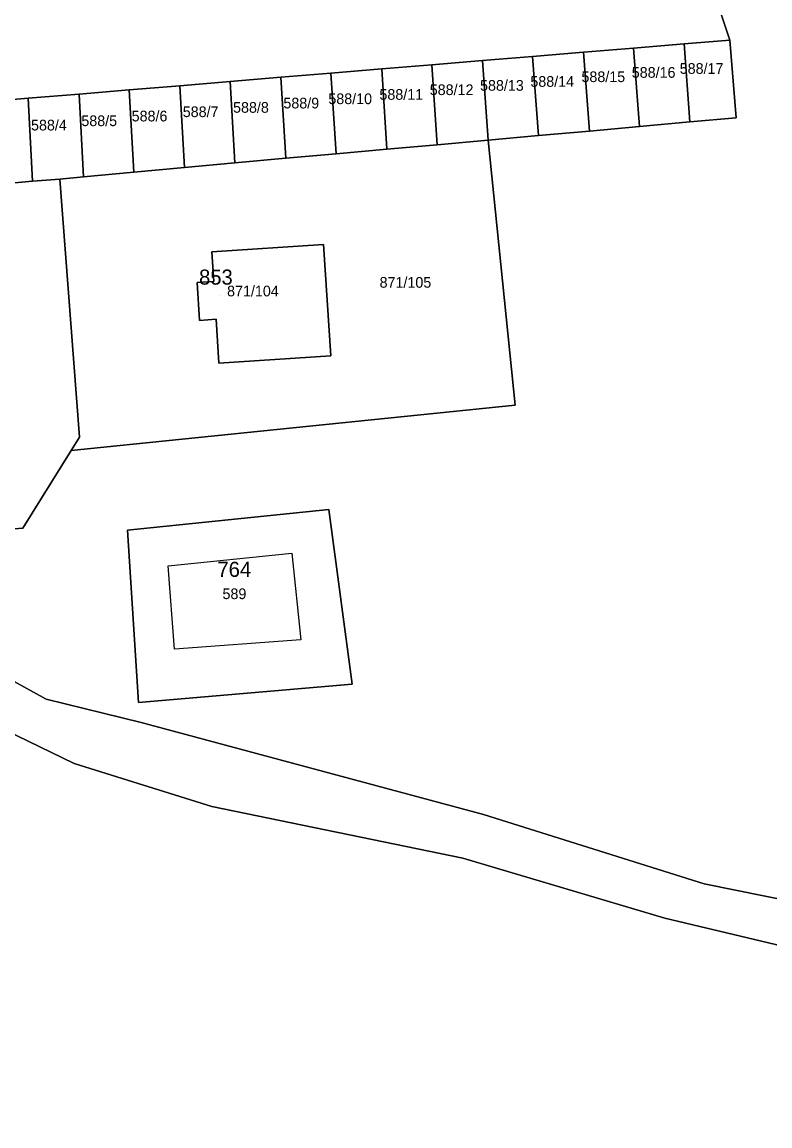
# Model space of a CAD drawing. Extents: x -873642 to -872917, y -1012962 to -1012567.
# Drawn here: x -873069.4 to -873009.9, y -1012787.3 to -1012699.6 of the extents above; entities that cross this region are included whole.
import ezdxf

# ---------------------------------------------------------------- set-up
doc = ezdxf.new("R2010")
doc.units = 0
for name, color, linetype in [('adresni_misto', 7, 'Continuous'), ('cisla_parcelni_kn', 7, 'Continuous'), ('cislo_domovni', 7, 'Continuous'), ('parcely_kn', 7, 'Continuous'), ('stavebni_objekty_bydleni', 7, 'Continuous'), ('stavebni_objekty_ostatni', 7, 'Continuous'), ('stavebni_objekty_vyroba', 7, 'Continuous')]:
    doc.layers.add(name, color=color, linetype=linetype)

msp = doc.modelspace()

# ---------------------------------------------------------------- linework, layer by layer
at = {"layer": 'adresni_misto'}
for p, q in [((-873053.71, -1012721.33), (-873053.71, -1012721.33)), ((-873052.25, -1012744.56), (-873052.25, -1012744.56))]:
    msp.add_line(p, q, dxfattribs=at)
at = {"layer": 'parcely_kn'}
for points in [[(-873074.59, -1012740.17), (-873069.33, -1012739.79), (-873065.48, -1012733.61), (-873030.18, -1012730.01), (-873032.33, -1012708.94), (-873028.33, -1012708.58), (-873024.28, -1012708.22), (-873020.29, -1012707.86), (-873016.29, -1012707.5), (-873012.61, -1012707.16), (-873013.12, -1012701), (-873016.82, -1012689.87), (-873017.19, -1012683.08), (-873019.32, -1012668.75), (-873020.42, -1012661.39), (-873025.64, -1012651.97), (-873026.14, -1012645.58), (-872990.98, -1012635.74)], [(-873074.59, -1012740.17), (-873069.33, -1012739.79), (-873065.48, -1012733.61), (-873030.18, -1012730.01), (-873032.33, -1012708.94), (-873028.33, -1012708.58), (-873024.28, -1012708.22), (-873020.29, -1012707.86), (-873016.29, -1012707.5), (-873012.61, -1012707.16), (-873013.12, -1012701), (-873016.82, -1012689.87), (-873017.19, -1012683.08), (-873019.32, -1012668.75), (-873020.42, -1012661.39), (-873025.64, -1012651.97), (-873026.14, -1012645.58), (-872990.98, -1012635.74)], [(-873016.82, -1012689.87), (-873013.12, -1012701), (-873016.73, -1012701.3), (-873020.77, -1012701.63), (-873024.75, -1012701.96), (-873028.79, -1012702.29), (-873032.77, -1012702.62), (-873036.81, -1012702.96), (-873040.79, -1012703.29), (-873044.83, -1012703.62), (-873048.81, -1012703.95), (-873052.85, -1012704.29), (-873056.83, -1012704.62), (-873060.87, -1012704.95), (-873064.85, -1012705.28), (-873068.89, -1012705.62), (-873072.87, -1012705.95)], [(-873016.82, -1012689.87), (-873013.12, -1012701), (-873016.73, -1012701.3), (-873020.77, -1012701.63), (-873024.75, -1012701.96), (-873028.79, -1012702.29), (-873032.77, -1012702.62), (-873036.81, -1012702.96), (-873040.79, -1012703.29), (-873044.83, -1012703.62), (-873048.81, -1012703.95), (-873052.85, -1012704.29), (-873056.83, -1012704.62), (-873060.87, -1012704.95), (-873064.85, -1012705.28), (-873068.89, -1012705.62), (-873072.87, -1012705.95)], [(-872958.67, -1012787.72), (-872975.04, -1012782.47), (-872991.42, -1012777.17), (-873018.29, -1012770.78), (-873034.35, -1012766.02), (-873054.3, -1012761.9), (-873065.25, -1012758.5), (-873079.89, -1012751.4), (-873100.03, -1012737.92), (-873105.65, -1012736.17), (-873101.03, -1012731.11), (-873099.7, -1012729.49), (-873098.43, -1012730.03), (-873097.94, -1012733.42), (-873081.4, -1012745.11), (-873078.44, -1012747.33), (-873067.46, -1012753.38), (-873059.91, -1012755.24), (-873032.7, -1012762.55), (-873015.14, -1012768.05), (-872991.17, -1012772.9), (-872969.11, -1012779.09), (-872954.48, -1012785.31), (-872943.22, -1012794.81)], [(-872958.67, -1012787.72), (-872975.04, -1012782.47), (-872991.42, -1012777.17), (-873018.29, -1012770.78), (-873034.35, -1012766.02), (-873054.3, -1012761.9), (-873065.25, -1012758.5), (-873079.89, -1012751.4), (-873100.03, -1012737.92), (-873105.65, -1012736.17), (-873101.03, -1012731.11), (-873099.7, -1012729.49), (-873098.43, -1012730.03), (-873097.94, -1012733.42), (-873081.4, -1012745.11), (-873078.44, -1012747.33), (-873067.46, -1012753.38), (-873059.91, -1012755.24), (-873032.7, -1012762.55), (-873015.14, -1012768.05), (-872991.17, -1012772.9), (-872969.11, -1012779.09), (-872954.48, -1012785.31), (-872943.22, -1012794.81)], [(-873185.58, -1012756.25), (-873148.18, -1012749.22), (-873135.01, -1012746.72), (-873122.26, -1012744.11), (-873114.5, -1012741.96), (-873110.07, -1012739.5), (-873105.65, -1012736.17), (-873100.03, -1012737.92), (-873079.89, -1012751.4), (-873065.25, -1012758.5), (-873054.3, -1012761.9), (-873034.35, -1012766.02), (-873018.29, -1012770.78), (-872991.42, -1012777.17), (-872975.04, -1012782.47), (-872958.67, -1012787.72)], [(-873185.58, -1012756.25), (-873148.18, -1012749.22), (-873135.01, -1012746.72), (-873122.26, -1012744.11), (-873114.5, -1012741.96), (-873110.07, -1012739.5), (-873105.65, -1012736.17), (-873100.03, -1012737.92), (-873079.89, -1012751.4), (-873065.25, -1012758.5), (-873054.3, -1012761.9), (-873034.35, -1012766.02), (-873018.29, -1012770.78), (-872991.42, -1012777.17), (-872975.04, -1012782.47), (-872958.67, -1012787.72)], [(-872991.17, -1012772.9), (-873015.14, -1012768.05), (-873032.7, -1012762.55), (-873059.91, -1012755.24), (-873067.46, -1012753.38), (-873078.44, -1012747.33)], [(-872991.17, -1012772.9), (-873015.14, -1012768.05), (-873032.7, -1012762.55), (-873059.91, -1012755.24), (-873067.46, -1012753.38), (-873078.44, -1012747.33)]]:
    msp.add_lwpolyline(points, dxfattribs=at)
for points in [[(-873012.61, -1012707.16), (-873016.29, -1012707.5), (-873016.73, -1012701.3), (-873013.12, -1012701)], [(-873012.61, -1012707.16), (-873016.29, -1012707.5), (-873016.73, -1012701.3), (-873013.12, -1012701)], [(-873024.75, -1012701.96), (-873024.28, -1012708.22), (-873028.33, -1012708.58), (-873028.79, -1012702.29)], [(-873024.75, -1012701.96), (-873024.28, -1012708.22), (-873028.33, -1012708.58), (-873028.79, -1012702.29)], [(-873020.77, -1012701.63), (-873020.29, -1012707.86), (-873024.28, -1012708.22), (-873024.75, -1012701.96)], [(-873020.77, -1012701.63), (-873020.29, -1012707.86), (-873024.28, -1012708.22), (-873024.75, -1012701.96)], [(-873016.73, -1012701.3), (-873016.29, -1012707.5), (-873020.29, -1012707.86), (-873020.77, -1012701.63)], [(-873016.73, -1012701.3), (-873016.29, -1012707.5), (-873020.29, -1012707.86), (-873020.77, -1012701.63)], [(-873032.77, -1012702.62), (-873032.33, -1012708.94), (-873036.38, -1012709.31), (-873036.81, -1012702.96)], [(-873032.77, -1012702.62), (-873032.33, -1012708.94), (-873036.38, -1012709.31), (-873036.81, -1012702.96)], [(-873028.79, -1012702.29), (-873028.33, -1012708.58), (-873032.33, -1012708.94), (-873032.77, -1012702.62)], [(-873028.79, -1012702.29), (-873028.33, -1012708.58), (-873032.33, -1012708.94), (-873032.77, -1012702.62)], [(-873044.83, -1012703.62), (-873044.42, -1012710.03), (-873048.42, -1012710.39), (-873048.81, -1012703.95)], [(-873044.83, -1012703.62), (-873044.42, -1012710.03), (-873048.42, -1012710.39), (-873048.81, -1012703.95)], [(-873040.79, -1012703.29), (-873040.37, -1012709.67), (-873044.42, -1012710.03), (-873044.83, -1012703.62)], [(-873040.79, -1012703.29), (-873040.37, -1012709.67), (-873044.42, -1012710.03), (-873044.83, -1012703.62)], [(-873036.81, -1012702.96), (-873036.38, -1012709.31), (-873040.37, -1012709.67), (-873040.79, -1012703.29)], [(-873036.81, -1012702.96), (-873036.38, -1012709.31), (-873040.37, -1012709.67), (-873040.79, -1012703.29)], [(-873056.83, -1012704.62), (-873056.46, -1012711.12), (-873060.51, -1012711.48), (-873060.87, -1012704.95)], [(-873056.83, -1012704.62), (-873056.46, -1012711.12), (-873060.51, -1012711.48), (-873060.87, -1012704.95)], [(-873052.85, -1012704.29), (-873052.47, -1012710.76), (-873056.46, -1012711.12), (-873056.83, -1012704.62)], [(-873052.85, -1012704.29), (-873052.47, -1012710.76), (-873056.46, -1012711.12), (-873056.83, -1012704.62)], [(-873048.81, -1012703.95), (-873048.42, -1012710.39), (-873052.47, -1012710.76), (-873052.85, -1012704.29)], [(-873048.81, -1012703.95), (-873048.42, -1012710.39), (-873052.47, -1012710.76), (-873052.85, -1012704.29)], [(-873064.85, -1012705.28), (-873064.51, -1012711.85), (-873066.38, -1012712.05), (-873068.55, -1012712.21), (-873068.89, -1012705.62)], [(-873064.85, -1012705.28), (-873064.51, -1012711.85), (-873066.38, -1012712.05), (-873068.55, -1012712.21), (-873068.89, -1012705.62)], [(-873060.87, -1012704.95), (-873060.51, -1012711.48), (-873064.51, -1012711.85), (-873064.85, -1012705.28)], [(-873060.87, -1012704.95), (-873060.51, -1012711.48), (-873064.51, -1012711.85), (-873064.85, -1012705.28)], [(-873068.89, -1012705.62), (-873068.55, -1012712.21), (-873071.45, -1012712.46), (-873072.55, -1012712.57), (-873072.87, -1012705.95)], [(-873068.89, -1012705.62), (-873068.55, -1012712.21), (-873071.45, -1012712.46), (-873072.55, -1012712.57), (-873072.87, -1012705.95)], [(-873065.48, -1012733.61), (-873064.82, -1012732.54), (-873066.38, -1012712.05), (-873064.51, -1012711.85), (-873060.51, -1012711.48), (-873056.46, -1012711.12), (-873052.47, -1012710.76), (-873048.42, -1012710.39), (-873044.42, -1012710.03), (-873040.37, -1012709.67), (-873036.38, -1012709.31), (-873032.33, -1012708.94), (-873030.18, -1012730.01)], [(-873065.48, -1012733.61), (-873064.82, -1012732.54), (-873066.38, -1012712.05), (-873064.51, -1012711.85), (-873060.51, -1012711.48), (-873056.46, -1012711.12), (-873052.47, -1012710.76), (-873048.42, -1012710.39), (-873044.42, -1012710.03), (-873040.37, -1012709.67), (-873036.38, -1012709.31), (-873032.33, -1012708.94), (-873030.18, -1012730.01)], [(-873071.45, -1012712.46), (-873068.55, -1012712.21), (-873066.38, -1012712.05), (-873064.82, -1012732.54), (-873065.48, -1012733.61), (-873069.33, -1012739.79), (-873074.59, -1012740.17), (-873098.43, -1012730.03), (-873099.7, -1012729.49), (-873097.47, -1012726.79), (-873090.67, -1012727.04), (-873069.98, -1012725.86), (-873070.53, -1012720.91)], [(-873071.45, -1012712.46), (-873068.55, -1012712.21), (-873066.38, -1012712.05), (-873064.82, -1012732.54), (-873065.48, -1012733.61), (-873069.33, -1012739.79), (-873074.59, -1012740.17), (-873098.43, -1012730.03), (-873099.7, -1012729.49), (-873097.47, -1012726.79), (-873090.67, -1012727.04), (-873069.98, -1012725.86), (-873070.53, -1012720.91)], [(-873045.43, -1012717.24), (-873044.84, -1012726.09), (-873053.73, -1012726.68), (-873053.94, -1012723.18), (-873055.27, -1012723.28), (-873055.47, -1012720.27), (-873054.13, -1012720.18), (-873054.29, -1012717.81)], [(-873054.29, -1012717.81), (-873054.13, -1012720.18), (-873055.47, -1012720.27), (-873055.27, -1012723.28), (-873053.94, -1012723.18), (-873053.73, -1012726.68), (-873044.84, -1012726.09), (-873045.43, -1012717.24)], [(-873045.43, -1012717.24), (-873044.84, -1012726.09), (-873053.73, -1012726.68), (-873053.94, -1012723.18), (-873055.27, -1012723.28), (-873055.47, -1012720.27), (-873054.13, -1012720.18), (-873054.29, -1012717.81)], [(-873054.29, -1012717.81), (-873054.13, -1012720.18), (-873055.47, -1012720.27), (-873055.27, -1012723.28), (-873053.94, -1012723.18), (-873053.73, -1012726.68), (-873044.84, -1012726.09), (-873045.43, -1012717.24)], [(-873061.01, -1012739.95), (-873044.99, -1012738.31), (-873043.15, -1012752.19), (-873060.12, -1012753.65)], [(-873043.15, -1012752.19), (-873044.99, -1012738.31), (-873061.01, -1012739.95), (-873060.12, -1012753.65)], [(-873061.01, -1012739.95), (-873044.99, -1012738.31), (-873043.15, -1012752.19), (-873060.12, -1012753.65)], [(-873043.15, -1012752.19), (-873044.99, -1012738.31), (-873061.01, -1012739.95), (-873060.12, -1012753.65)]]:
    msp.add_lwpolyline(points, close=True, dxfattribs=at)
at = {"layer": 'stavebni_objekty_bydleni'}
msp.add_lwpolyline([(-873045.43, -1012717.24), (-873044.84, -1012726.09), (-873053.73, -1012726.68), (-873053.94, -1012723.18), (-873055.27, -1012723.28), (-873055.47, -1012720.27), (-873054.13, -1012720.18), (-873054.29, -1012717.81)], close=True, dxfattribs=at)
at = {"layer": 'stavebni_objekty_ostatni'}
for points in [[(-873016.73, -1012701.3), (-873013.12, -1012701), (-873012.61, -1012707.16), (-873016.29, -1012707.5)], [(-873028.33, -1012708.58), (-873028.79, -1012702.29), (-873024.75, -1012701.96), (-873024.28, -1012708.22)], [(-873024.75, -1012701.96), (-873020.77, -1012701.63), (-873020.29, -1012707.86), (-873024.28, -1012708.22)], [(-873020.29, -1012707.86), (-873020.77, -1012701.63), (-873016.73, -1012701.3), (-873016.29, -1012707.5)], [(-873032.77, -1012702.62), (-873032.33, -1012708.94), (-873036.38, -1012709.31), (-873036.81, -1012702.96)], [(-873032.77, -1012702.62), (-873028.79, -1012702.29), (-873028.33, -1012708.58), (-873032.33, -1012708.94)], [(-873044.83, -1012703.62), (-873044.42, -1012710.03), (-873048.42, -1012710.39), (-873048.81, -1012703.95)], [(-873040.79, -1012703.29), (-873040.37, -1012709.67), (-873044.42, -1012710.03), (-873044.83, -1012703.62)], [(-873036.81, -1012702.96), (-873036.38, -1012709.31), (-873040.37, -1012709.67), (-873040.79, -1012703.29)], [(-873056.83, -1012704.62), (-873056.46, -1012711.12), (-873060.51, -1012711.48), (-873060.87, -1012704.95)], [(-873052.85, -1012704.29), (-873052.47, -1012710.76), (-873056.46, -1012711.12), (-873056.83, -1012704.62)], [(-873048.81, -1012703.95), (-873048.42, -1012710.39), (-873052.47, -1012710.76), (-873052.85, -1012704.29)], [(-873064.85, -1012705.28), (-873064.51, -1012711.85), (-873066.38, -1012712.05), (-873068.55, -1012712.21), (-873068.89, -1012705.62)], [(-873060.87, -1012704.95), (-873060.51, -1012711.48), (-873064.51, -1012711.85), (-873064.85, -1012705.28)], [(-873068.89, -1012705.62), (-873068.55, -1012712.21), (-873071.45, -1012712.46), (-873072.55, -1012712.57), (-873072.87, -1012705.95)]]:
    msp.add_lwpolyline(points, close=True, dxfattribs=at)
at = {"layer": 'stavebni_objekty_vyroba'}
msp.add_lwpolyline([(-873057.27, -1012749.41), (-873057.77, -1012742.79), (-873047.94, -1012741.76), (-873047.22, -1012748.65)], close=True, dxfattribs=at)

# ---------------------------------------------------------------- texts
at = {"layer": 'cisla_parcelni_kn'}
for s, p in [('588/17', (-873017.096, -1012703.675)), ('588/17', (-873017.096, -1012703.675)), ('588/15', (-873024.908, -1012704.331)), ('588/15', (-873024.908, -1012704.331)), ('588/16', (-873020.908, -1012703.988)), ('588/16', (-873020.908, -1012703.988)), ('588/12', (-873036.971, -1012705.363)), ('588/12', (-873036.971, -1012705.363)), ('588/13', (-873032.971, -1012705.019)), ('588/13', (-873032.971, -1012705.019)), ('588/14', (-873028.971, -1012704.706)), ('588/14', (-873028.971, -1012704.706)), ('588/10', (-873045.033, -1012706.081)), ('588/10', (-873045.033, -1012706.081)), ('588/11', (-873040.971, -1012705.738)), ('588/11', (-873040.971, -1012705.738)), ('588/7', (-873056.608, -1012707.113)), ('588/7', (-873056.608, -1012707.113)), ('588/8', (-873052.608, -1012706.769)), ('588/8', (-873052.608, -1012706.769)), ('588/9', (-873048.608, -1012706.425)), ('588/9', (-873048.608, -1012706.425)), ('588/4', (-873068.671, -1012708.175)), ('588/4', (-873068.671, -1012708.175)), ('588/5', (-873064.671, -1012707.831)), ('588/5', (-873064.671, -1012707.831)), ('588/6', (-873060.671, -1012707.456)), ('588/6', (-873060.671, -1012707.456)), ('871/105', (-873040.958, -1012720.675)), ('871/105', (-873040.958, -1012720.675)), ('871/104', (-873053.083, -1012721.363)), ('871/104', (-873053.083, -1012721.363)), ('589', (-873053.446, -1012745.425)), ('589', (-873053.446, -1012745.425))]:
    msp.add_text(s, height=0.85, dxfattribs=at).set_placement(p)
at = {"layer": 'cislo_domovni'}
for s, p in [('853', (-873055.31, -1012720.43)), ('764', (-873053.85, -1012743.66))]:
    msp.add_text(s, height=1.2, dxfattribs=at).set_placement(p)

doc.saveas('drawing.dxf')
